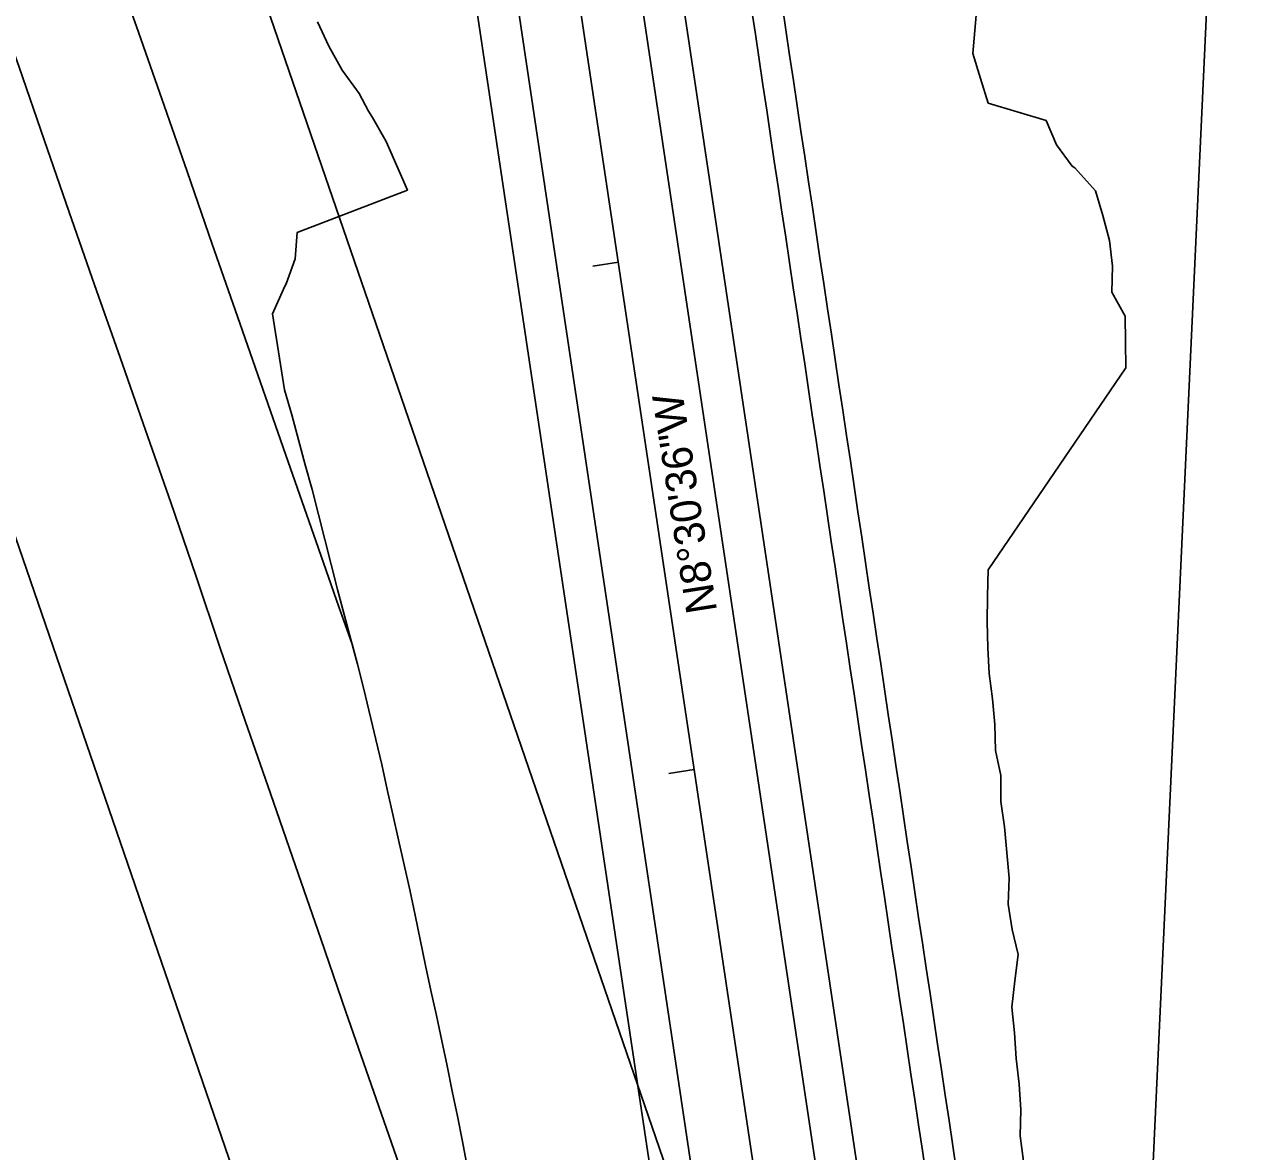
# Model space of a CAD drawing. Extents: x 609264 to 611265, y 427753 to 431566.
# Drawn here: x 610888.4 to 611125.9, y 428813.2 to 429032.9 of the extents above; entities that cross this region are included whole.
import ezdxf

# ---------------------------------------------------------------- set-up
doc = ezdxf.new("R2010")
doc.units = 0
for name, color, linetype in [('R_Drainage', 7, 'Continuous'), ('R_Horz Alg', 7, 'Continuous'), ('R_Horz Alg Station', 7, 'Continuous'), ('R_Horz Bearings', 7, 'Continuous'), ('R_Obliterate', 7, 'Continuous'), ('R_Proposed Const Limits', 7, 'Continuous'), ('R_Proposed Const Limits S2', 7, 'Continuous'), ('R_Proposed Road', 7, 'Continuous'), ('R_Proposed Shoulder', 7, 'Continuous'), ('R_Restraining Conditions', 7, 'Continuous'), ('R_ROW', 7, 'Continuous'), ('S_EXIST_ROW', 7, 'Continuous')]:
    doc.layers.add(name, color=color, linetype=linetype)

msp = doc.modelspace()

# ---------------------------------------------------------------- linework, layer by layer
at = {"layer": 'R_Drainage'}
for points in [[(611070.15, 428809.39), (611069.41, 428814.33), (611068.67, 428819.28), (611067.93, 428824.22), (611067.19, 428829.17), (611066.45, 428834.11), (611065.71, 428839.06), (611064.97, 428844), (611064.23, 428848.95), (611063.49, 428853.89), (611062.75, 428858.84), (611062.01, 428863.78), (611061.27, 428868.72), (611060.53, 428873.67), (611059.79, 428878.61), (611059.05, 428883.56), (611058.31, 428888.5), (611057.57, 428893.45), (611056.83, 428898.39), (611056.09, 428903.34), (611055.35, 428908.28), (611054.61, 428913.23), (611053.87, 428918.17), (611053.13, 428923.12), (611052.39, 428928.06), (611051.65, 428933.01), (611050.91, 428937.95), (611050.17, 428942.9), (611049.43, 428947.84), (611048.69, 428952.79), (611047.95, 428957.73), (611047.21, 428962.68), (611046.47, 428967.62), (611045.73, 428972.57), (611044.99, 428977.51), (611044.25, 428982.46), (611043.51, 428987.4), (611042.77, 428992.35), (611042.03, 428997.29), (611041.97, 428997.71), (611041.29, 429002.24), (611040.55, 429007.18), (611039.81, 429012.13), (611039.07, 429017.07), (611038.33, 429022.02), (611037.59, 429026.96), (611036.85, 429031.91), (611036.11, 429036.85)], [(611064.21, 428808.5), (611063.47, 428813.44), (611062.73, 428818.39), (611061.99, 428823.33), (611061.25, 428828.28), (611060.51, 428833.22), (611059.77, 428838.17), (611059.03, 428843.11), (611058.29, 428848.06), (611057.55, 428853), (611056.81, 428857.95), (611056.07, 428862.89), (611055.33, 428867.84), (611054.59, 428872.78), (611053.85, 428877.73), (611053.11, 428882.67), (611052.37, 428887.62), (611051.63, 428892.56), (611050.89, 428897.51), (611050.15, 428902.45), (611049.41, 428907.4), (611048.67, 428912.34), (611047.93, 428917.29), (611047.19, 428922.23), (611046.45, 428927.18), (611045.71, 428932.12), (611044.97, 428937.07), (611044.23, 428942.01), (611043.49, 428946.96), (611042.75, 428951.9), (611042.01, 428956.85), (611041.27, 428961.79), (611040.53, 428966.74), (611039.79, 428971.68), (611039.05, 428976.63), (611038.31, 428981.57), (611037.57, 428986.52), (611036.83, 428991.46), (611036.09, 428996.41), (611036.03, 428996.82), (611035.35, 429001.35), (611034.61, 429006.3), (611033.87, 429011.24), (611033.14, 429016.19), (611032.4, 429021.13), (611031.66, 429026.08), (611030.92, 429031.02), (611030.18, 429035.97)]]:
    msp.add_lwpolyline(points, dxfattribs=at)
at = {"layer": 'R_Horz Alg'}
msp.add_line((611107.78, 428294.28), (610909.26, 429621.04), dxfattribs=at)
at = {"layer": 'R_Horz Alg Station'}
for points in [[(610999.25, 428985.84), (611004.2, 428986.58)], [(611014.05, 428886.94), (611019, 428887.68)]]:
    msp.add_lwpolyline(points, dxfattribs=at)
at = {"layer": 'R_Obliterate'}
for p, q in [((610952.28, 428912.11), (610949.74, 428919.39)), ((610952.28, 428912.11), (610949.74, 428919.39)), ((610953.35, 428908.19), (610952.28, 428912.11)), ((610960.23, 428878.89), (610959.16, 428883.78)), ((610961.32, 428873.99), (610960.23, 428878.89)), ((610963.55, 428864.22), (610961.32, 428873.99)), ((610964.61, 428859.32), (610963.55, 428864.22))]:
    msp.add_line(p, q, dxfattribs=at)
for points in [[(610949.74, 428919.39), (610944.79, 428933.54), (610939.84, 428947.68), (610934.89, 428961.84), (610929.95, 428976), (610925.03, 428990.09), (610920.12, 429004.24), (610915.22, 429018.41), (610910.28, 429032.53), (610905.2, 429046.79), (610900.13, 429060.88), (610895.06, 429074.96), (610889.94, 429089.04), (610884.83, 429103.09), (610879.7, 429117.17), (610874.63, 429131.27), (610869.49, 429145.36), (610864.32, 429159.44), (610861.3, 429167.65), (610857.91, 429177.14), (610852.75, 429191.2), (610847.64, 429205.34), (610842.61, 429219.43), (610839.19, 429229.17)], [(610949.74, 428919.39), (610944.79, 428933.54), (610939.84, 428947.68), (610934.89, 428961.84), (610929.95, 428976), (610925.03, 428990.09), (610920.12, 429004.24), (610915.22, 429018.41), (610910.28, 429032.53), (610905.2, 429046.79), (610900.13, 429060.88), (610895.06, 429074.96), (610889.94, 429089.04), (610884.83, 429103.09), (610879.7, 429117.17), (610874.63, 429131.27), (610869.49, 429145.36), (610864.32, 429159.44), (610861.3, 429167.65), (610857.91, 429177.14), (610852.75, 429191.2), (610847.64, 429205.34), (610842.61, 429219.43), (610839.19, 429229.17)], [(610882.37, 429038.56), (610887.37, 429024.62), (610892.25, 429010.47), (610897.14, 428996.31), (610902.07, 428982.17), (610907.05, 428967.98), (610912.02, 428953.85), (610916.96, 428939.72), (610921.8, 428925.53), (610926.59, 428911.33), (610931.46, 428897.15), (610936.41, 428883), (610941.29, 428868.88), (610946.18, 428854.7), (610951.1, 428840.46), (610956.02, 428826.29), (610960.93, 428812.12), (610965.73, 428798.1), (610970.48, 428783.88), (610975.1, 428769.66), (610979.74, 428755.4), (610984.4, 428741.15), (610989.09, 428726.9), (610989.22, 428726.5)], [(610882.37, 429038.56), (610887.37, 429024.62), (610892.25, 429010.47), (610897.14, 428996.31), (610902.07, 428982.17), (610907.05, 428967.98), (610912.02, 428953.85), (610916.96, 428939.72), (610921.8, 428925.53), (610926.59, 428911.33), (610931.46, 428897.15), (610936.41, 428883), (610941.29, 428868.88), (610946.18, 428854.7), (610951.1, 428840.46), (610956.02, 428826.29), (610960.93, 428812.12), (610965.73, 428798.1), (610970.48, 428783.88), (610975.1, 428769.66), (610979.74, 428755.4), (610984.4, 428741.15), (610989.09, 428726.9), (610989.22, 428726.5)], [(610974.71, 428810.27), (610973.84, 428815.2), (610972.82, 428820.1), (610971.78, 428825), (610970.8, 428829.91), (610969.82, 428834.82), (610968.75, 428839.71), (610967.66, 428844.61), (610966.63, 428849.51), (610964.61, 428859.32), (610963.55, 428864.22), (610961.32, 428873.99), (610960.23, 428878.89), (610959.16, 428883.78), (610958.08, 428888.67), (610956.94, 428893.56), (610954.6, 428903.32), (610953.35, 428908.19), (610952.28, 428912.11)], [(610959.16, 428883.78), (610958.08, 428888.67), (610956.94, 428893.56), (610954.6, 428903.32), (610953.35, 428908.19)], [(610968.75, 428839.71), (610967.66, 428844.61), (610966.63, 428849.51), (610964.61, 428859.32)], [(610976.8, 428800.47), (610975.72, 428805.37), (610974.71, 428810.27), (610973.84, 428815.2), (610972.82, 428820.1), (610971.78, 428825), (610970.8, 428829.91), (610969.82, 428834.82), (610968.75, 428839.71)]]:
    msp.add_lwpolyline(points, dxfattribs=at)
at = {"layer": 'R_Proposed Const Limits'}
for points in [[(611075.99, 429057.99), (611073.3, 429027.25), (611074.78, 429022.42), (611076.3, 429017.59), (611087.58, 429014.22), (611089.6, 429009.47), (611092.65, 429005.29), (611093.19, 429004.95), (611097.25, 429000.5), (611098.67, 428995.66), (611099.98, 428990.8), (611100.53, 428985.82), (611100.38, 428980.75), (611102.99, 428976.08), (611103.08, 428971.04), (611103.17, 428966), (611076.28, 428926.58)], [(610939.14, 428961.71), (610938.34, 428966.61), (610936.76, 428976.49), (610939.21, 428981.91), (610939.45, 428982.37), (610941.21, 428987.26), (610941.57, 428992.37), (610963.09, 429000.65), (610961.01, 429005.39), (610958.94, 429010.14), (610956.24, 429014.79), (610955.51, 429016.05), (610953.7, 429019.47), (610950.33, 429024.02), (610947.79, 429028.69), (610945.54, 429033.41)], [(611076.28, 428926.58), (611076.15, 428921.51), (611076.12, 428916.45), (611076.22, 428911.41), (611076.52, 428906.4), (611077.17, 428901.44), (611077.59, 428896.45), (611077.76, 428891.42), (611078.8, 428886.52), (611078.77, 428881.46), (611079.51, 428876.51), (611079.97, 428871.52), (611080.41, 428866.53), (611080.22, 428861.45), (611080.99, 428856.51), (611082.12, 428851.62), (611081.49, 428846.47), (611080.9, 428841.33), (611081.45, 428836.35), (611081.75, 428831.35), (611082.32, 428826.37), (611082.68, 428821.37), (611082.57, 428816.3), (611083.19, 428811.34)]]:
    msp.add_lwpolyline(points, dxfattribs=at)
at = {"layer": 'R_Proposed Const Limits S2'}
msp.add_lwpolyline([(610974.71, 428810.27), (610973.84, 428815.2), (610972.82, 428820.1), (610971.78, 428825), (610970.8, 428829.91), (610969.82, 428834.82), (610968.75, 428839.71), (610967.66, 428844.61), (610966.63, 428849.51), (610964.61, 428859.32), (610963.55, 428864.22), (610961.32, 428873.99), (610960.23, 428878.89), (610959.16, 428883.78), (610958.08, 428888.67), (610956.94, 428893.56), (610954.6, 428903.32), (610953.35, 428908.19), (610952.03, 428913.05), (610950.74, 428917.91), (610949.48, 428922.78), (610948.23, 428927.65), (610946.97, 428932.51), (610945.72, 428937.38), (610944.48, 428942.25), (610943.17, 428947.11), (610940.52, 428956.83), (610939.14, 428961.68), (610939.14, 428961.71)], dxfattribs=at)
at = {"layer": 'R_Proposed Road'}
for p, q in [((611100.64, 428423.11), (610921.13, 429622.82)), ((611041.57, 428655.73), (610897.4, 429619.26))]:
    msp.add_line(p, q, dxfattribs=at)
at = {"layer": 'R_Proposed Shoulder'}
for p, q in [((611112.77, 428396.14), (610929.04, 429624)), ((611025.84, 428706.82), (610889.48, 429618.08))]:
    msp.add_line(p, q, dxfattribs=at)
at = {"layer": 'R_Restraining Conditions'}
msp.add_line((610794.84, 429199.86), (610963.05, 428710.9), dxfattribs=at)
at = {"layer": 'R_ROW'}
msp.add_lwpolyline([(611107.97, 428799.88), (611125.91, 429186.79), (611015.56, 429741.88)], dxfattribs=at)
at = {"layer": 'S_EXIST_ROW'}
for p, q in [((611038.7, 428736.93), (610840.72, 429312.43)), ((610963.05, 428710.9), (610794.84, 429199.86))]:
    msp.add_line(p, q, dxfattribs=at)

# ---------------------------------------------------------------- texts
at = {"layer": 'R_Horz Bearings'}
msp.add_text('N8%%d30\'36"W', height=6, rotation=99.0104, dxfattribs=at).set_placement((611023.47, 428918.61))

doc.saveas('drawing.dxf')
